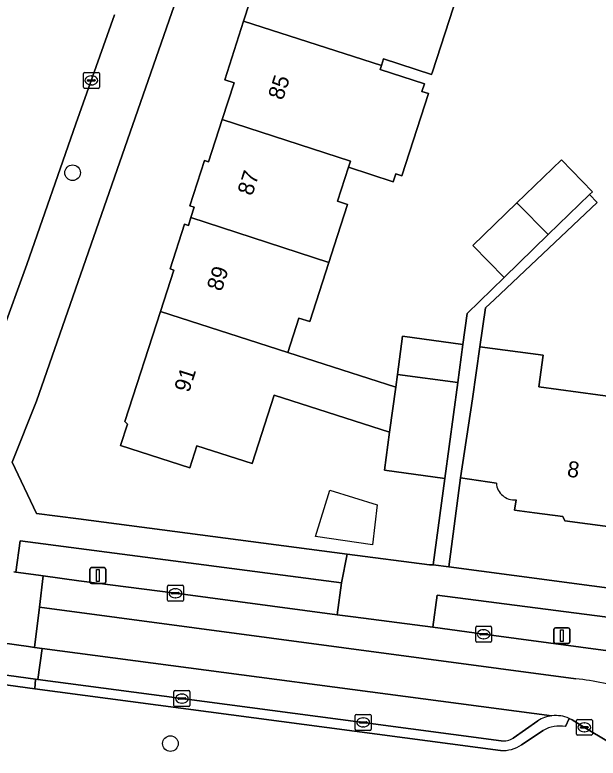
# Model space of a CAD drawing. Extents: x 161402 to 161933, y 381647 to 382315.
# Drawn here: x 161754.11 to 161790.64, y 381673.61 to 381720.22 of the extents above; entities that cross this region are included whole.
import ezdxf

# ---------------------------------------------------------------- set-up
doc = ezdxf.new("R2010")
doc.units = 0
for name, color, linetype in [('IMGEO_Berm_groen', 7, 'Continuous'), ('IMGEO_Boom', 7, 'Continuous'), ('IMGEO_Erf', 7, 'Continuous'), ('IMGEO_Groenvoorziening', 7, 'Continuous'), ('IMGEO_Kolk', 7, 'Continuous'), ('IMGEO_Lichtmast', 7, 'Continuous'), ('IMGEO_Pand', 7, 'Continuous'), ('IMGEO_Pand_nummerreeks', 7, 'Continuous'), ('IMGEO_Pand_vergunning_verleend', 7, 'Continuous'), ('IMGEO_Parkeervlak_open', 7, 'Continuous'), ('IMGEO_Rijbaan_lokaal_gesloten', 7, 'Continuous'), ('IMGEO_Rijbaan_lokaal_open', 7, 'Continuous'), ('IMGEO_Voetpad_open', 7, 'Continuous')]:
    doc.layers.add(name, color=color, linetype=linetype)

msp = doc.modelspace()

# ---------------------------------------------------------------- linework, layer by layer
at = {"layer": 'IMGEO_Berm_groen'}
for points in [[(161784.529, 381674.098), (161755.36, 381677.968), (161729.565, 381681.519), (161651.186, 381692.31), (161606.834, 381698.381), (161606.888, 381698.815), (161607.041, 381699.033)], [(161800.409, 381669.174), (161789.78, 381675.544), (161789.016, 381676.015), (161788.825, 381676.108), (161788.602, 381675.587)], [(161787.201, 381675.354), (161785.846, 381674.444)]]:
    msp.add_lwpolyline(points, dxfattribs=at)
for centre, radius, start, end in [((161788.21, 381673.614), 2.012, 78.7738, 120.111), ((161784.686, 381676.18), 2.088, 265.6855, 303.7546)]:
    msp.add_arc(centre, radius, start, end, dxfattribs=at)
at = {"layer": 'IMGEO_Boom'}
for centre in [(161757.727, 381710.316), (161763.852, 381674.528)]:
    msp.add_circle(centre, 0.489, dxfattribs=at)
at = {"layer": 'IMGEO_Erf'}
for points in [[(161767.515, 381730.653), (161755.462, 381695.988), (161753.951, 381692.163), (161755.465, 381688.954), (161758.095, 381688.61), (161774.933, 381686.404), (161780.075, 381685.73), (161780.312, 381685.735), (161781.032, 381691.152), (161777.26, 381691.663), (161777.583, 381694.042), (161770.348, 381696.372), (161768.967, 381692.089), (161765.514, 381693.203), (161765.068, 381691.819), (161760.733, 381693.217), (161761.162, 381694.548), (161761.002, 381694.725), (161763.227, 381701.624), (161764.064, 381704.217), (161763.836, 381704.29), (161764.739, 381707.088), (161764.976, 381707.012), (161765.14, 381707.52), (161765.342, 381708.149), (161765.079, 381708.234), (161765.998, 381711.084), (161766.242, 381711.005), (161767.099, 381713.662), (161767.841, 381715.963), (161767.254, 381716.152), (161768.436, 381719.817), (161769.594, 381723.408)], [(161781.826, 381721.497), (161780.266, 381716.653), (161780.21, 381716.479), (161777.199, 381717.451), (161777.065, 381717.036), (161776.985, 381716.789), (161779.765, 381715.893), (161779.609, 381715.41), (161780.015, 381715.279), (161778.354, 381710.13), (161777.971, 381710.254), (161777.809, 381709.753), (161775.008, 381710.656), (161774.323, 381708.534), (161774.952, 381708.33), (161774.117, 381705.74), (161773.781, 381704.698), (161772.582, 381700.981), (161771.905, 381701.199), (161771.213, 381699.052), (161777.967, 381696.877), (161778.075, 381697.672), (161778.399, 381700.063), (161782.171, 381699.551), (161782.435, 381701.499), (161784.755, 381703.749), (161782.801, 381705.758), (161785.523, 381708.399), (161788.343, 381711.135), (161790.298, 381709.126), (161790.111, 381708.944), (161790.59, 381708.45), (161784.155, 381702.376), (161783.591, 381701.843), (161783.242, 381699.406), (161787.203, 381698.874), (161786.935, 381696.897), (161793.095, 381696.061)], [(161784.271, 381690.852), (161782.028, 381691.189), (161781.286, 381685.605), (161785.387, 381685.06), (161810.335, 381681.743), (161810.864, 381685.721)], [(161810.864, 381685.721), (161808.013, 381686.108), (161807.987, 381685.916), (161805.076, 381686.311), (161805.108, 381686.546), (161804.442, 381686.636), (161803.987, 381686.698), (161803.951, 381686.434), (161801.004, 381686.834), (161801.031, 381687.037), (161798.265, 381687.412), (161795.543, 381687.782), (161795.51, 381687.543), (161792.563, 381687.942), (161792.6, 381688.213), (161792.005, 381688.294), (161791.432, 381688.372), (161791.396, 381688.106), (161788.552, 381688.492), (161788.44, 381688.767), (161786.652, 381688.992), (161785.408, 381689.17), (161785.5, 381689.813)]]:
    msp.add_lwpolyline(points, dxfattribs=at)
msp.add_arc((161785.386, 381690.925), 1.117, 183.729, 275.8484, dxfattribs=at)
at = {"layer": 'IMGEO_Groenvoorziening'}
for points in [[(161774.573, 381684.604), (161754.441, 381687.245), (161754.178, 381685.267), (161755.59, 381685.076), (161755.889, 381685.036), (161758.113, 381684.736), (161764.17, 381683.951), (161774.303, 381682.604)], [(161780.28, 381681.817), (161783.474, 381681.383), (161797.978, 381679.434), (161801.769, 381678.925), (161816.794, 381676.903), (161817.073, 381679.111), (161780.562, 381683.829)]]:
    msp.add_lwpolyline(points, close=True, dxfattribs=at)
at = {"layer": 'IMGEO_Kolk'}
for p, q in [((161758.402, 381715.682), (161758.402, 381716.534)), ((161758.477, 381716.608), (161759.329, 381716.608)), ((161759.403, 381716.534), (161759.403, 381715.682)), ((161758.661, 381716.102), (161758.661, 381716.114)), ((161759.099, 381716.065), (161758.701, 381716.065)), ((161758.704, 381716.151), (161759.102, 381716.151)), ((161758.89, 381716.388), (161758.915, 381716.388)), ((161759.145, 381716.114), (161759.145, 381716.102)), ((161759.329, 381715.608), (161758.477, 381715.608)), ((161758.913, 381715.828), (161758.888, 381715.828)), ((161763.669, 381683.525), (161763.669, 381684.377)), ((161763.744, 381684.451), (161764.596, 381684.451)), ((161764.67, 381684.377), (161764.67, 381683.525)), ((161763.928, 381683.945), (161763.928, 381683.957)), ((161764.366, 381683.908), (161763.968, 381683.908)), ((161763.971, 381683.994), (161764.369, 381683.994)), ((161764.157, 381684.231), (161764.182, 381684.231)), ((161764.412, 381683.957), (161764.412, 381683.945)), ((161764.596, 381683.451), (161763.744, 381683.451)), ((161764.18, 381683.671), (161764.155, 381683.671)), ((161782.973, 381680.957), (161782.973, 381681.809)), ((161783.048, 381681.883), (161783.9, 381681.883)), ((161783.461, 381681.663), (161783.486, 381681.663)), ((161783.974, 381681.809), (161783.974, 381680.957)), ((161783.232, 381681.377), (161783.232, 381681.389)), ((161783.67, 381681.34), (161783.272, 381681.34)), ((161783.275, 381681.426), (161783.673, 381681.426)), ((161783.484, 381681.103), (161783.459, 381681.103)), ((161783.716, 381681.389), (161783.716, 381681.377)), ((161783.9, 381680.883), (161783.048, 381680.883)), ((161764.073, 381676.921), (161764.073, 381677.773)), ((161764.148, 381677.847), (161765, 381677.847)), ((161765.074, 381677.773), (161765.074, 381676.921)), ((161764.332, 381677.341), (161764.332, 381677.353)), ((161764.77, 381677.304), (161764.372, 381677.304)), ((161764.375, 381677.39), (161764.773, 381677.39)), ((161764.561, 381677.627), (161764.586, 381677.627)), ((161764.816, 381677.353), (161764.816, 381677.341)), ((161765, 381676.847), (161764.148, 381676.847)), ((161764.584, 381677.067), (161764.559, 381677.067)), ((161775.502, 381676.353), (161776.354, 381676.353)), ((161775.427, 381675.427), (161775.427, 381676.279)), ((161775.729, 381675.896), (161776.127, 381675.896)), ((161775.915, 381676.133), (161775.94, 381676.133)), ((161776.428, 381676.279), (161776.428, 381675.427)), ((161789.279, 381675.118), (161789.279, 381675.97)), ((161789.354, 381676.044), (161790.206, 381676.044)), ((161790.28, 381675.97), (161790.28, 381675.118)), ((161775.686, 381675.847), (161775.686, 381675.859)), ((161776.124, 381675.81), (161775.726, 381675.81)), ((161775.938, 381675.573), (161775.913, 381675.573)), ((161776.17, 381675.859), (161776.17, 381675.847)), ((161789.538, 381675.538), (161789.538, 381675.55)), ((161789.976, 381675.501), (161789.578, 381675.501)), ((161789.581, 381675.587), (161789.979, 381675.587)), ((161789.767, 381675.824), (161789.792, 381675.824)), ((161790.022, 381675.55), (161790.022, 381675.538)), ((161776.354, 381675.353), (161775.502, 381675.353)), ((161790.206, 381675.044), (161789.354, 381675.044)), ((161789.79, 381675.264), (161789.765, 381675.264))]:
    msp.add_line(p, q, dxfattribs=at)
for points in [[(161758.402, 381715.682), (161758.402, 381716.534)], [(161758.477, 381716.608), (161759.329, 381716.608)], [(161759.403, 381716.534), (161759.403, 381715.682)], [(161759.329, 381715.608), (161758.477, 381715.608)], [(161763.669, 381683.525), (161763.669, 381684.377)], [(161763.744, 381684.451), (161764.596, 381684.451)], [(161764.67, 381684.377), (161764.67, 381683.525)], [(161764.596, 381683.451), (161763.744, 381683.451)], [(161782.973, 381680.957), (161782.973, 381681.809)], [(161783.048, 381681.883), (161783.9, 381681.883)], [(161783.974, 381681.809), (161783.974, 381680.957)], [(161783.9, 381680.883), (161783.048, 381680.883)], [(161764.073, 381676.921), (161764.073, 381677.773)], [(161764.148, 381677.847), (161765, 381677.847)], [(161765.074, 381677.773), (161765.074, 381676.921)], [(161765, 381676.847), (161764.148, 381676.847)], [(161775.502, 381676.353), (161776.354, 381676.353)], [(161775.427, 381675.427), (161775.427, 381676.279)], [(161776.428, 381676.279), (161776.428, 381675.427)], [(161789.279, 381675.118), (161789.279, 381675.97)], [(161789.354, 381676.044), (161790.206, 381676.044)], [(161790.28, 381675.97), (161790.28, 381675.118)], [(161776.354, 381675.353), (161775.502, 381675.353)], [(161790.206, 381675.044), (161789.354, 381675.044)]]:
    msp.add_lwpolyline(points, dxfattribs=at)
for centre, radius, start, end in [((161758.479, 381716.532), 0.0765, 91.552, 178.448), ((161758.479, 381716.532), 0.0765, 91.552, 178.448), ((161759.327, 381716.532), 0.0765, 1.552, 88.448), ((161759.327, 381716.532), 0.0765, 1.552, 88.448), ((161758.701, 381716.111), 0.0403, 85.8775, 175.7526), ((161758.698, 381716.101), 0.0366, 178.938, 274.7102), ((161759.102, 381716.108), 0.043, 264.8664, 352.4533), ((161759.106, 381716.113), 0.0386, 1.7309, 96.639), ((161758.479, 381715.684), 0.0765, 181.552, 268.448), ((161758.479, 381715.684), 0.0765, 181.552, 268.448), ((161759.327, 381715.684), 0.0765, 271.552, 358.448), ((161759.327, 381715.684), 0.0765, 271.552, 358.448), ((161763.746, 381684.375), 0.0765, 91.552, 178.448), ((161763.746, 381684.375), 0.0765, 91.552, 178.448), ((161764.594, 381684.375), 0.0765, 1.552, 88.448), ((161764.594, 381684.375), 0.0765, 1.552, 88.448), ((161763.968, 381683.954), 0.0403, 85.8775, 175.7526), ((161763.965, 381683.944), 0.0366, 178.938, 274.7102), ((161764.369, 381683.951), 0.043, 264.8664, 352.4533), ((161764.373, 381683.956), 0.0386, 1.7309, 96.639), ((161763.746, 381683.527), 0.0765, 181.552, 268.448), ((161763.746, 381683.527), 0.0765, 181.552, 268.448), ((161764.594, 381683.527), 0.0765, 271.552, 358.448), ((161764.594, 381683.527), 0.0765, 271.552, 358.448), ((161783.05, 381681.807), 0.0765, 91.552, 178.448), ((161783.05, 381681.807), 0.0765, 91.552, 178.448), ((161783.898, 381681.807), 0.0765, 1.552, 88.448), ((161783.898, 381681.807), 0.0765, 1.552, 88.448), ((161783.272, 381681.386), 0.0403, 85.8775, 175.7526), ((161783.269, 381681.376), 0.0366, 178.938, 274.7102), ((161783.673, 381681.383), 0.043, 264.8664, 352.4533), ((161783.677, 381681.388), 0.0386, 1.7309, 96.639), ((161783.05, 381680.959), 0.0765, 181.552, 268.448), ((161783.05, 381680.959), 0.0765, 181.552, 268.448), ((161783.898, 381680.959), 0.0765, 271.552, 358.448), ((161783.898, 381680.959), 0.0765, 271.552, 358.448), ((161764.15, 381677.771), 0.0765, 91.552, 178.448), ((161764.15, 381677.771), 0.0765, 91.552, 178.448), ((161764.998, 381677.771), 0.0765, 1.552, 88.448), ((161764.998, 381677.771), 0.0765, 1.552, 88.448), ((161764.372, 381677.35), 0.0403, 85.8775, 175.7526), ((161764.369, 381677.34), 0.0366, 178.938, 274.7102), ((161764.773, 381677.347), 0.043, 264.8664, 352.4533), ((161764.777, 381677.352), 0.0386, 1.7309, 96.639), ((161764.15, 381676.923), 0.0765, 181.552, 268.448), ((161764.15, 381676.923), 0.0765, 181.552, 268.448), ((161764.998, 381676.923), 0.0765, 271.552, 358.448), ((161764.998, 381676.923), 0.0765, 271.552, 358.448), ((161775.504, 381676.277), 0.0765, 91.552, 178.448), ((161775.504, 381676.277), 0.0765, 91.552, 178.448), ((161776.352, 381676.277), 0.0765, 1.552, 88.448), ((161776.352, 381676.277), 0.0765, 1.552, 88.448), ((161775.726, 381675.856), 0.0403, 85.8775, 175.7526), ((161776.131, 381675.858), 0.0386, 1.7309, 96.639), ((161789.356, 381675.968), 0.0765, 91.552, 178.448), ((161789.356, 381675.968), 0.0765, 91.552, 178.448), ((161790.204, 381675.968), 0.0765, 1.552, 88.448), ((161790.204, 381675.968), 0.0765, 1.552, 88.448), ((161775.504, 381675.429), 0.0765, 181.552, 268.448), ((161775.504, 381675.429), 0.0765, 181.552, 268.448), ((161775.723, 381675.846), 0.0366, 178.938, 274.7102), ((161776.127, 381675.853), 0.043, 264.8664, 352.4533), ((161776.352, 381675.429), 0.0765, 271.552, 358.448), ((161776.352, 381675.429), 0.0765, 271.552, 358.448), ((161789.578, 381675.547), 0.0403, 85.8775, 175.7526), ((161789.575, 381675.537), 0.0366, 178.938, 274.7102), ((161789.979, 381675.544), 0.043, 264.8664, 352.4533), ((161789.983, 381675.549), 0.0386, 1.7309, 96.639), ((161789.356, 381675.12), 0.0765, 181.552, 268.448), ((161789.356, 381675.12), 0.0765, 181.552, 268.448), ((161790.204, 381675.12), 0.0765, 271.552, 358.448), ((161790.204, 381675.12), 0.0765, 271.552, 358.448)]:
    msp.add_arc(centre, radius, start, end, dxfattribs=at)
for centre, major_axis, ratio, start_param, end_param in [((161758.889, 381716.108), (-0.387, 0.002), 0.722429, 4.712389, 7.853982), ((161758.914, 381716.108), (-0.39, 0.002), 0.717154, 1.570796, 4.712389), ((161764.156, 381683.951), (-0.387, 0.002), 0.722429, 4.712389, 7.853982), ((161764.181, 381683.951), (-0.39, 0.002), 0.717154, 1.570796, 4.712389), ((161783.46, 381681.383), (-0.387, 0.002), 0.722429, 4.712389, 7.853982), ((161783.485, 381681.383), (-0.39, 0.002), 0.717154, 1.570796, 4.712389), ((161764.56, 381677.347), (-0.387, 0.002), 0.722429, 4.712389, 7.853982), ((161764.585, 381677.347), (-0.39, 0.002), 0.717154, 1.570796, 4.712389), ((161775.914, 381675.853), (-0.387, 0.002), 0.722429, 4.712389, 7.853982), ((161775.939, 381675.853), (-0.39, 0.002), 0.717154, 1.570796, 4.712389), ((161789.766, 381675.544), (-0.387, 0.002), 0.722429, 4.712389, 7.853982), ((161789.791, 381675.544), (-0.39, 0.002), 0.717154, 1.570796, 4.712389)]:
    msp.add_ellipse(centre, major_axis=major_axis, ratio=ratio, start_param=start_param, end_param=end_param, dxfattribs=at)
at = {"layer": 'IMGEO_Lichtmast'}
for p, q in [((161758.811, 381684.656), (161758.811, 381685.456)), ((161758.811, 381685.456), (161758.811, 381684.656)), ((161758.911, 381685.556), (161759.701, 381685.556)), ((161759.701, 381685.556), (161758.911, 381685.556)), ((161759.801, 381685.456), (161759.801, 381684.656)), ((161759.801, 381684.656), (161759.801, 381685.456)), ((161759.701, 381684.556), (161758.911, 381684.556)), ((161758.911, 381684.556), (161759.701, 381684.556)), ((161787.875, 381680.892), (161787.875, 381681.692)), ((161787.875, 381681.692), (161787.875, 381680.892)), ((161787.975, 381681.792), (161788.765, 381681.792)), ((161788.765, 381681.792), (161787.975, 381681.792)), ((161788.865, 381681.692), (161788.865, 381680.892)), ((161788.865, 381680.892), (161788.865, 381681.692)), ((161788.765, 381680.792), (161787.975, 381680.792)), ((161787.975, 381680.792), (161788.765, 381680.792))]:
    msp.add_line(p, q, dxfattribs=at)
for points in [[(161759.231, 381685.431), (161759.381, 381685.431), (161759.381, 381684.681), (161759.231, 381684.681), (161759.231, 381685.431)], [(161788.295, 381681.667), (161788.445, 381681.667), (161788.445, 381680.917), (161788.295, 381680.917), (161788.295, 381681.667)]]:
    msp.add_lwpolyline(points, dxfattribs=at)
for centre, start, end in [((161758.911, 381685.456), 90, 180), ((161758.911, 381685.456), 90, 180), ((161759.701, 381685.456), 0, 90), ((161759.701, 381685.456), 360, 90), ((161758.911, 381684.656), 180, 270), ((161758.911, 381684.656), 180, 270), ((161759.701, 381684.656), 270, 0), ((161759.701, 381684.656), 270, 0), ((161787.975, 381681.692), 90, 180), ((161787.975, 381681.692), 90, 180), ((161788.765, 381681.692), 0, 90), ((161788.765, 381681.692), 360, 90), ((161787.975, 381680.892), 180, 270), ((161787.975, 381680.892), 180, 270), ((161788.765, 381680.892), 270, 0), ((161788.765, 381680.892), 270, 0)]:
    msp.add_arc(centre, 0.1, start, end, dxfattribs=at)
at = {"layer": 'IMGEO_Pand'}
for points in [[(161778.951, 381722.883), (161770.897, 381725.48), (161770.168, 381723.222), (161769.594, 381723.408), (161768.436, 381719.817), (161777.065, 381717.036), (161777.199, 381717.451), (161780.21, 381716.479), (161780.266, 381716.653), (161781.826, 381721.497), (161778.817, 381722.468)], [(161777.065, 381717.036), (161768.436, 381719.817), (161767.254, 381716.152), (161767.841, 381715.963), (161767.099, 381713.662), (161775.131, 381711.038), (161775.008, 381710.656), (161777.809, 381709.753), (161777.971, 381710.254), (161778.354, 381710.13), (161780.015, 381715.279), (161779.609, 381715.41), (161779.765, 381715.893), (161776.985, 381716.789)], [(161775.008, 381710.656), (161775.131, 381711.038), (161767.099, 381713.662), (161766.242, 381711.005), (161765.998, 381711.084), (161765.079, 381708.234), (161765.342, 381708.149), (161765.14, 381707.52), (161773.781, 381704.698), (161774.117, 381705.74), (161774.952, 381708.33), (161774.323, 381708.534)], [(161790.298, 381709.126), (161788.343, 381711.135), (161785.523, 381708.399), (161785.622, 381708.375), (161787.523, 381706.434), (161790.111, 381708.944)], [(161787.523, 381706.434), (161785.622, 381708.375), (161785.523, 381708.399), (161782.801, 381705.758), (161784.755, 381703.749)], [(161763.227, 381701.624), (161771.213, 381699.052), (161771.905, 381701.199), (161772.582, 381700.981), (161773.781, 381704.698), (161765.14, 381707.52), (161764.976, 381707.012), (161764.739, 381707.088), (161763.836, 381704.29), (161764.064, 381704.217)], [(161763.227, 381701.624), (161761.002, 381694.725), (161761.162, 381694.548), (161760.733, 381693.217), (161765.068, 381691.819), (161765.514, 381693.203), (161768.967, 381692.089), (161770.348, 381696.372), (161777.583, 381694.042), (161777.967, 381696.877), (161771.213, 381699.052)], [(161781.847, 381697.16), (161782.171, 381699.551), (161778.399, 381700.063), (161778.075, 381697.672)], [(161781.847, 381697.16), (161778.075, 381697.672), (161777.967, 381696.877), (161777.583, 381694.042), (161777.26, 381691.663), (161781.032, 381691.152)]]:
    msp.add_lwpolyline(points, close=True, dxfattribs=at)
msp.add_lwpolyline([(161785.5, 381689.813), (161785.408, 381689.17), (161786.652, 381688.992), (161788.44, 381688.767), (161788.552, 381688.492), (161791.396, 381688.106), (161791.432, 381688.372), (161792.005, 381688.294), (161793.095, 381696.061), (161786.935, 381696.897), (161787.203, 381698.874), (161783.242, 381699.406), (161782.773, 381696.134), (161782.028, 381691.189), (161784.271, 381690.852)], dxfattribs=at)
msp.add_arc((161785.386, 381690.925), 1.117, 183.729, 275.8484, dxfattribs=at)
at = {"layer": 'IMGEO_Pand_vergunning_verleend'}
msp.add_lwpolyline([(161772.951, 381687.518), (161773.841, 381690.415), (161776.797, 381689.505), (161776.509, 381686.983)], close=True, dxfattribs=at)
at = {"layer": 'IMGEO_Parkeervlak_open'}
for points in [[(161607.169, 381698.958), (161634.017, 381695.281), (161655.284, 381692.339), (161663.643, 381691.165), (161672.558, 381689.965), (161694.81, 381686.893), (161713.098, 381684.403), (161730.381, 381682.01), (161755.406, 381678.561), (161755.55, 381678.541), (161755.812, 381680.487), (161755.342, 381680.553), (161754.955, 381680.607), (161731.533, 381683.878), (161713.959, 381686.299), (161671.18, 381692.191)], [(161787.753, 381676.267), (161755.812, 381680.487), (161755.55, 381678.541)], [(161755.55, 381678.541), (161764.574, 381677.347), (161775.928, 381675.853), (161784.575, 381674.706)], [(161785.325, 381674.864), (161786.863, 381675.949)]]:
    msp.add_lwpolyline(points, dxfattribs=at)
for centre, radius, start, end in [((161787.938, 381674.345), 1.93, 95.4929, 123.8311), ((161784.732, 381675.821), 1.126, 262.0017, 301.791)]:
    msp.add_arc(centre, radius, start, end, dxfattribs=at)
at = {"layer": 'IMGEO_Rijbaan_lokaal_gesloten'}
for points in [[(161783.474, 381681.383), (161780.28, 381681.817), (161775.305, 381682.472), (161774.303, 381682.604), (161764.17, 381683.951), (161758.113, 381684.736), (161755.889, 381685.036), (161755.649, 381683.069), (161789.238, 381678.584)], [(161797.391, 381676.3), (161797.978, 381679.434), (161783.474, 381681.383)]]:
    msp.add_lwpolyline(points, dxfattribs=at)
msp.add_arc((161787.891, 381664.361), 14.287, 70.4853, 84.5882, dxfattribs=at)
at = {"layer": 'IMGEO_Rijbaan_lokaal_open'}
for points in [[(161752.637, 381722.762), (161751.781, 381720.237), (161748.444, 381710.397), (161745.751, 381703.186), (161744.072, 381698.382), (161743.353, 381696.426), (161750.867, 381693.658), (161751.631, 381695.709), (161754.863, 381704.566), (161757.922, 381713.379), (161759.437, 381717.619), (161760.349, 381720.224)], [(161734.953, 381688.284), (161733.538, 381688.452), (161732.145, 381688.644), (161731.533, 381683.878), (161754.955, 381680.607), (161755.342, 381680.553), (161755.649, 381683.069), (161755.889, 381685.036), (161755.59, 381685.076), (161754.178, 381685.267), (161754.045, 381685.285)], [(161789.238, 381678.584), (161755.649, 381683.069), (161755.342, 381680.553), (161755.812, 381680.487), (161787.753, 381676.267)], [(161788.825, 381676.108), (161789.016, 381676.015), (161789.78, 381675.544), (161800.409, 381669.174)]]:
    msp.add_lwpolyline(points, dxfattribs=at)
for centre, radius, start, end in [((161787.891, 381664.361), 14.287, 70.4853, 84.5882), ((161787.995, 381674.208), 2.073, 66.4141, 96.7126)]:
    msp.add_arc(centre, radius, start, end, dxfattribs=at)
at = {"layer": 'IMGEO_Voetpad_open'}
for points in [[(161754.045, 381685.285), (161754.178, 381685.267), (161754.441, 381687.245), (161774.573, 381684.604), (161774.933, 381686.404), (161758.095, 381688.61), (161755.465, 381688.954), (161753.951, 381692.163), (161755.462, 381695.988), (161767.515, 381730.653), (161773.48, 381750), (161778.317, 381767.408)], [(161760.349, 381720.224), (161759.437, 381717.619), (161757.922, 381713.379), (161754.863, 381704.566), (161751.631, 381695.709), (161750.867, 381693.658), (161750.152, 381691.742)], [(161607.041, 381699.033), (161606.888, 381698.815), (161606.834, 381698.381), (161651.186, 381692.31), (161729.565, 381681.519), (161755.36, 381677.968), (161755.406, 381678.561), (161730.381, 381682.01), (161713.098, 381684.403), (161694.81, 381686.893), (161672.558, 381689.965), (161663.643, 381691.165), (161655.284, 381692.339), (161634.017, 381695.281), (161607.169, 381698.958)], [(161785.387, 381685.06), (161781.286, 381685.605), (161780.312, 381685.735), (161780.075, 381685.73), (161774.933, 381686.404), (161774.573, 381684.604), (161774.303, 381682.604), (161775.305, 381682.472), (161780.28, 381681.817), (161780.562, 381683.829), (161817.073, 381679.111), (161816.794, 381676.903), (161817.079, 381676.869), (161828.401, 381675.346)], [(161836.324, 381679.597), (161837.329, 381681.964), (161835.307, 381682.579), (161830.604, 381683.472), (161830.531, 381683.085), (161824.917, 381684.151), (161824.343, 381679.854), (161816.889, 381680.871), (161811.416, 381681.599), (161810.335, 381681.743), (161785.387, 381685.06)], [(161755.55, 381678.541), (161755.406, 381678.561), (161755.36, 381677.968), (161784.529, 381674.098)], [(161784.575, 381674.706), (161775.928, 381675.853), (161764.574, 381677.347), (161755.55, 381678.541)], [(161786.863, 381675.949), (161785.325, 381674.864)], [(161788.602, 381675.587), (161788.825, 381676.108)], [(161785.846, 381674.444), (161787.201, 381675.354)]]:
    msp.add_lwpolyline(points, dxfattribs=at)
msp.add_lwpolyline([(161784.155, 381702.376), (161790.59, 381708.45), (161790.111, 381708.944), (161787.523, 381706.434), (161784.755, 381703.749), (161782.435, 381701.499), (161782.171, 381699.551), (161781.847, 381697.16), (161781.032, 381691.152), (161780.312, 381685.735), (161781.286, 381685.605), (161782.028, 381691.189), (161782.773, 381696.134), (161783.242, 381699.406), (161783.591, 381701.843)], close=True, dxfattribs=at)
for centre, radius, start, end in [((161787.938, 381674.345), 1.93, 95.4929, 123.8311), ((161787.995, 381674.208), 2.073, 66.4141, 96.7126), ((161788.21, 381673.614), 2.012, 78.7738, 120.111), ((161784.732, 381675.821), 1.126, 262.0017, 301.791), ((161784.686, 381676.18), 2.088, 265.6855, 303.7546)]:
    msp.add_arc(centre, radius, start, end, dxfattribs=at)

# ---------------------------------------------------------------- texts
at = {"layer": 'IMGEO_Pand_nummerreeks'}
for s, rotation, p in [('85', 72.2557, (161770.894, 381714.82)), ('87', 72.2557, (161768.976, 381708.827)), ('89', 72.2542, (161767.058, 381702.834)), ('91', 72.1209, (161765.018, 381696.489)), ('8', 352.2841, (161788.659, 381691.273))]:
    msp.add_text(s, height=1, rotation=rotation, dxfattribs=at).set_placement(p)

doc.saveas('drawing.dxf')
